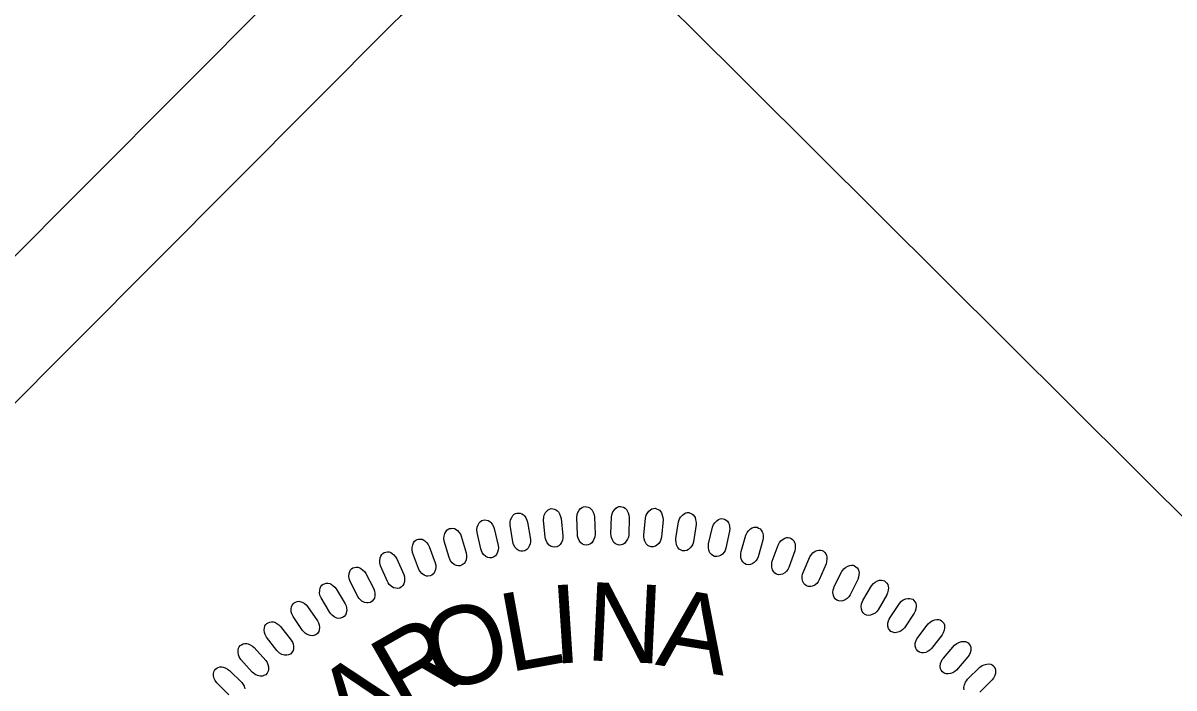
# Model space of a CAD drawing. Extents: x 1481763 to 1495577, y 493394 to 506245.
# Drawn here: x 1489881 to 1490047.4, y 499065.5 to 499161.7 of the extents above; entities that cross this region are included whole.
import ezdxf

# ---------------------------------------------------------------- set-up
doc = ezdxf.new("R2010")
doc.units = 0
for name, color, linetype in [('Old_Level_9', 7, 'Continuous'), ('Sheet Sticker Exception Certification CELL', 7, 'Continuous'), ('Sheet Title CELL', 7, 'Continuous')]:
    doc.layers.add(name, color=color, linetype=linetype)

msp = doc.modelspace()

# ---------------------------------------------------------------- linework, layer by layer
at = {"layer": 'Old_Level_9'}
for points in [[(1489956.48, 499087.36), (1489956.24, 499089.81), (1489956.28, 499090.25), (1489956.35, 499090.54), (1489956.54, 499090.9), (1489956.72, 499091.13), (1489956.92, 499091.31), (1489957.12, 499091.41), (1489957.35, 499091.47), (1489957.57, 499091.46), (1489957.82, 499091.42), (1489958.04, 499091.32), (1489958.26, 499091.14), (1489958.4, 499091), (1489958.56, 499090.71), (1489958.71, 499090.36), (1489958.79, 499090.05), (1489959.04, 499087.55), (1489959.03, 499087.21), (1489958.97, 499086.92), (1489958.82, 499086.59), (1489958.63, 499086.29), (1489958.45, 499086.11), (1489958.15, 499085.96), (1489957.85, 499085.89), (1489957.55, 499085.94), (1489957.33, 499086.02), (1489957.06, 499086.2), (1489956.79, 499086.51), (1489956.62, 499086.86), (1489956.53, 499087.11)], [(1489961.13, 499087.74), (1489961.04, 499090.19), (1489961.1, 499090.63), (1489961.2, 499090.91), (1489961.41, 499091.26), (1489961.6, 499091.49), (1489961.82, 499091.65), (1489962.02, 499091.74), (1489962.25, 499091.79), (1489962.47, 499091.75), (1489962.71, 499091.7), (1489962.93, 499091.59), (1489963.14, 499091.4), (1489963.27, 499091.24), (1489963.41, 499090.95), (1489963.54, 499090.59), (1489963.6, 499090.28), (1489963.7, 499087.76), (1489963.66, 499087.42), (1489963.58, 499087.14), (1489963.41, 499086.82), (1489963.2, 499086.53), (1489963.01, 499086.36), (1489962.7, 499086.23), (1489962.4, 499086.18), (1489962.1, 499086.25), (1489961.89, 499086.35), (1489961.63, 499086.54), (1489961.38, 499086.87), (1489961.23, 499087.22), (1489961.16, 499087.48)], [(1489965.99, 499087.82), (1489966.06, 499090.27), (1489966.15, 499090.71), (1489966.26, 499090.99), (1489966.49, 499091.32), (1489966.69, 499091.53), (1489966.92, 499091.68), (1489967.14, 499091.76), (1489967.36, 499091.79), (1489967.58, 499091.74), (1489967.82, 499091.68), (1489968.03, 499091.55), (1489968.23, 499091.35), (1489968.34, 499091.18), (1489968.47, 499090.88), (1489968.58, 499090.52), (1489968.62, 499090.2), (1489968.55, 499087.68), (1489968.5, 499087.35), (1489968.4, 499087.07), (1489968.21, 499086.76), (1489967.98, 499086.48), (1489967.78, 499086.33), (1489967.46, 499086.22), (1489967.16, 499086.19), (1489966.87, 499086.28), (1489966.66, 499086.38), (1489966.41, 499086.59), (1489966.19, 499086.94), (1489966.06, 499087.3), (1489966.01, 499087.56)], [(1489970.74, 499087.64), (1489970.96, 499090.08), (1489971.08, 499090.51), (1489971.21, 499090.78), (1489971.46, 499091.1), (1489971.68, 499091.3), (1489971.91, 499091.44), (1489972.13, 499091.5), (1489972.36, 499091.52), (1489972.58, 499091.46), (1489972.81, 499091.37), (1489973.01, 499091.24), (1489973.2, 499091.02), (1489973.3, 499090.85), (1489973.41, 499090.54), (1489973.49, 499090.17), (1489973.51, 499089.85), (1489973.29, 499087.34), (1489973.22, 499087.01), (1489973.1, 499086.74), (1489972.89, 499086.44), (1489972.64, 499086.18), (1489972.43, 499086.04), (1489972.11, 499085.95), (1489971.81, 499085.94), (1489971.52, 499086.05), (1489971.32, 499086.16), (1489971.09, 499086.39), (1489970.88, 499086.75), (1489970.78, 499087.12), (1489970.74, 499087.38)], [(1489975.38, 499087.14), (1489975.76, 499089.56), (1489975.9, 499089.98), (1489976.05, 499090.24), (1489976.32, 499090.54), (1489976.55, 499090.73), (1489976.79, 499090.85), (1489977.01, 499090.9), (1489977.24, 499090.9), (1489977.46, 499090.83), (1489977.68, 499090.73), (1489977.87, 499090.58), (1489978.05, 499090.35), (1489978.14, 499090.18), (1489978.23, 499089.86), (1489978.29, 499089.49), (1489978.29, 499089.17), (1489977.91, 499086.68), (1489977.81, 499086.35), (1489977.68, 499086.09), (1489977.46, 499085.8), (1489977.19, 499085.56), (1489976.97, 499085.43), (1489976.65, 499085.36), (1489976.34, 499085.37), (1489976.06, 499085.5), (1489975.87, 499085.63), (1489975.65, 499085.86), (1489975.47, 499086.24), (1489975.39, 499086.61), (1489975.37, 499086.88)], [(1489947.17, 499085.64), (1489946.63, 499088.03), (1489946.61, 499088.48), (1489946.65, 499088.77), (1489946.79, 499089.15), (1489946.94, 499089.41), (1489947.12, 499089.62), (1489947.31, 499089.74), (1489947.52, 499089.83), (1489947.74, 499089.84), (1489947.99, 499089.83), (1489948.22, 499089.76), (1489948.47, 499089.61), (1489948.62, 499089.48), (1489948.82, 499089.22), (1489949.01, 499088.9), (1489949.13, 499088.6), (1489949.69, 499086.15), (1489949.72, 499085.81), (1489949.7, 499085.51), (1489949.59, 499085.16), (1489949.44, 499084.84), (1489949.28, 499084.64), (1489949, 499084.46), (1489948.72, 499084.35), (1489948.41, 499084.37), (1489948.18, 499084.42), (1489947.89, 499084.55), (1489947.58, 499084.83), (1489947.37, 499085.15), (1489947.26, 499085.39)], [(1489951.8, 499086.68), (1489951.41, 499089.1), (1489951.41, 499089.55), (1489951.47, 499089.84), (1489951.64, 499090.21), (1489951.8, 499090.46), (1489951.99, 499090.65), (1489952.19, 499090.76), (1489952.4, 499090.84), (1489952.63, 499090.83), (1489952.88, 499090.81), (1489953.1, 499090.73), (1489953.34, 499090.56), (1489953.49, 499090.42), (1489953.67, 499090.15), (1489953.84, 499089.81), (1489953.94, 499089.5), (1489954.35, 499087.03), (1489954.36, 499086.68), (1489954.31, 499086.39), (1489954.19, 499086.05), (1489954.01, 499085.74), (1489953.84, 499085.55), (1489953.55, 499085.38), (1489953.26, 499085.3), (1489952.95, 499085.33), (1489952.73, 499085.39), (1489952.45, 499085.55), (1489952.16, 499085.85), (1489951.97, 499086.18), (1489951.87, 499086.43)], [(1489980.11, 499086.38), (1489980.65, 499088.77), (1489980.81, 499089.18), (1489980.98, 499089.43), (1489981.27, 499089.72), (1489981.51, 499089.89), (1489981.76, 499090), (1489981.98, 499090.03), (1489982.21, 499090.02), (1489982.42, 499089.93), (1489982.64, 499089.82), (1489982.82, 499089.66), (1489982.98, 499089.42), (1489983.06, 499089.24), (1489983.13, 499088.91), (1489983.17, 499088.54), (1489983.14, 499088.22), (1489982.61, 499085.76), (1489982.49, 499085.44), (1489982.35, 499085.19), (1489982.1, 499084.91), (1489981.82, 499084.69), (1489981.6, 499084.58), (1489981.27, 499084.53), (1489980.97, 499084.55), (1489980.69, 499084.7), (1489980.51, 499084.84), (1489980.3, 499085.09), (1489980.14, 499085.47), (1489980.09, 499085.85), (1489980.09, 499086.12)], [(1489942.59, 499084.4), (1489941.9, 499086.75), (1489941.85, 499087.19), (1489941.87, 499087.49), (1489941.99, 499087.88), (1489942.12, 499088.14), (1489942.29, 499088.36), (1489942.46, 499088.5), (1489942.67, 499088.6), (1489942.9, 499088.62), (1489943.14, 499088.63), (1489943.38, 499088.58), (1489943.63, 499088.44), (1489943.79, 499088.32), (1489944.01, 499088.07), (1489944.22, 499087.76), (1489944.35, 499087.47), (1489945.07, 499085.06), (1489945.13, 499084.72), (1489945.12, 499084.43), (1489945.04, 499084.07), (1489944.9, 499083.74), (1489944.76, 499083.53), (1489944.49, 499083.33), (1489944.21, 499083.21), (1489943.9, 499083.2), (1489943.67, 499083.24), (1489943.37, 499083.36), (1489943.05, 499083.62), (1489942.82, 499083.92), (1489942.69, 499084.16)], [(1489984.8, 499085.27), (1489985.48, 499087.63), (1489985.67, 499088.03), (1489985.85, 499088.27), (1489986.16, 499088.53), (1489986.41, 499088.69), (1489986.67, 499088.78), (1489986.89, 499088.8), (1489987.12, 499088.77), (1489987.32, 499088.67), (1489987.53, 499088.55), (1489987.7, 499088.38), (1489987.85, 499088.13), (1489987.92, 499087.94), (1489987.97, 499087.62), (1489987.98, 499087.24), (1489987.94, 499086.92), (1489987.25, 499084.5), (1489987.12, 499084.19), (1489986.95, 499083.94), (1489986.69, 499083.69), (1489986.4, 499083.48), (1489986.17, 499083.38), (1489985.83, 499083.35), (1489985.53, 499083.4), (1489985.27, 499083.56), (1489985.1, 499083.71), (1489984.91, 499083.97), (1489984.77, 499084.36), (1489984.74, 499084.75), (1489984.76, 499085.01)], [(1489938.15, 499082.82), (1489937.32, 499085.13), (1489937.24, 499085.56), (1489937.24, 499085.86), (1489937.34, 499086.26), (1489937.44, 499086.53), (1489937.6, 499086.76), (1489937.77, 499086.9), (1489937.97, 499087.02), (1489938.19, 499087.05), (1489938.44, 499087.08), (1489938.68, 499087.04), (1489938.94, 499086.92), (1489939.11, 499086.81), (1489939.34, 499086.58), (1489939.57, 499086.28), (1489939.72, 499086), (1489940.59, 499083.64), (1489940.66, 499083.3), (1489940.67, 499083.01), (1489940.61, 499082.65), (1489940.5, 499082.31), (1489940.37, 499082.09), (1489940.12, 499081.87), (1489939.85, 499081.74), (1489939.54, 499081.71), (1489939.31, 499081.73), (1489939, 499081.83), (1489938.66, 499082.07), (1489938.41, 499082.36), (1489938.27, 499082.59)], [(1489989.31, 499083.9), (1489990.14, 499086.21), (1489990.36, 499086.6), (1489990.55, 499086.83), (1489990.88, 499087.07), (1489991.13, 499087.21), (1489991.4, 499087.28), (1489991.62, 499087.29), (1489991.85, 499087.25), (1489992.05, 499087.14), (1489992.25, 499087), (1489992.41, 499086.82), (1489992.54, 499086.56), (1489992.6, 499086.37), (1489992.62, 499086.04), (1489992.61, 499085.66), (1489992.55, 499085.35), (1489991.71, 499082.98), (1489991.56, 499082.67), (1489991.38, 499082.44), (1489991.1, 499082.2), (1489990.8, 499082.01), (1489990.56, 499081.93), (1489990.22, 499081.92), (1489989.93, 499081.98), (1489989.68, 499082.16), (1489989.51, 499082.33), (1489989.34, 499082.6), (1489989.23, 499083), (1489989.22, 499083.38), (1489989.26, 499083.65)], [(1489933.67, 499080.96), (1489932.69, 499083.21), (1489932.58, 499083.64), (1489932.56, 499083.94), (1489932.64, 499084.34), (1489932.73, 499084.62), (1489932.87, 499084.86), (1489933.03, 499085.01), (1489933.22, 499085.14), (1489933.44, 499085.19), (1489933.68, 499085.23), (1489933.92, 499085.21), (1489934.19, 499085.11), (1489934.37, 499085.01), (1489934.61, 499084.79), (1489934.86, 499084.51), (1489935.03, 499084.23), (1489936.05, 499081.93), (1489936.14, 499081.6), (1489936.17, 499081.31), (1489936.13, 499080.95), (1489936.04, 499080.6), (1489935.92, 499080.38), (1489935.68, 499080.14), (1489935.43, 499079.99), (1489935.12, 499079.94), (1489934.89, 499079.95), (1489934.58, 499080.03), (1489934.22, 499080.25), (1489933.95, 499080.52), (1489933.8, 499080.74)], [(1489993.76, 499082.24), (1489994.73, 499084.49), (1489994.97, 499084.86), (1489995.18, 499085.08), (1489995.52, 499085.3), (1489995.78, 499085.43), (1489996.05, 499085.48), (1489996.28, 499085.48), (1489996.5, 499085.42), (1489996.69, 499085.3), (1489996.88, 499085.15), (1489997.03, 499084.96), (1489997.14, 499084.69), (1489997.19, 499084.5), (1489997.19, 499084.17), (1489997.16, 499083.79), (1489997.08, 499083.48), (1489996.1, 499081.17), (1489995.92, 499080.87), (1489995.73, 499080.65), (1489995.44, 499080.43), (1489995.12, 499080.26), (1489994.88, 499080.19), (1489994.54, 499080.21), (1489994.25, 499080.29), (1489994.01, 499080.48), (1489993.86, 499080.65), (1489993.7, 499080.94), (1489993.62, 499081.34), (1489993.64, 499081.73), (1489993.68, 499081.99)], [(1489929.4, 499078.76), (1489928.28, 499080.95), (1489928.15, 499081.37), (1489928.12, 499081.67), (1489928.16, 499082.07), (1489928.24, 499082.36), (1489928.36, 499082.6), (1489928.51, 499082.77), (1489928.69, 499082.9), (1489928.91, 499082.97), (1489929.15, 499083.03), (1489929.39, 499083.02), (1489929.67, 499082.93), (1489929.85, 499082.84), (1489930.1, 499082.64), (1489930.37, 499082.37), (1489930.56, 499082.11), (1489931.72, 499079.88), (1489931.83, 499079.56), (1489931.88, 499079.27), (1489931.87, 499078.9), (1489931.79, 499078.55), (1489931.69, 499078.32), (1489931.47, 499078.07), (1489931.22, 499077.9), (1489930.92, 499077.84), (1489930.69, 499077.83), (1489930.37, 499077.89), (1489930, 499078.08), (1489929.72, 499078.34), (1489929.55, 499078.55)], [(1489998.27, 499080.21), (1489999.38, 499082.4), (1489999.65, 499082.76), (1489999.87, 499082.96), (1490000.22, 499083.16), (1490000.49, 499083.27), (1490000.77, 499083.31), (1490000.99, 499083.28), (1490001.21, 499083.22), (1490001.39, 499083.08), (1490001.57, 499082.92), (1490001.71, 499082.72), (1490001.8, 499082.44), (1490001.84, 499082.25), (1490001.82, 499081.92), (1490001.77, 499081.55), (1490001.66, 499081.24), (1490000.54, 499078.99), (1490000.35, 499078.71), (1490000.14, 499078.5), (1489999.83, 499078.3), (1489999.51, 499078.15), (1489999.26, 499078.1), (1489998.93, 499078.13), (1489998.64, 499078.23), (1489998.41, 499078.44), (1489998.27, 499078.62), (1489998.13, 499078.92), (1489998.07, 499079.33), (1489998.12, 499079.71), (1489998.18, 499079.97)], [(1490002.4, 499078.2), (1490003.65, 499080.31), (1490003.93, 499080.65), (1490004.17, 499080.84), (1490004.53, 499081.02), (1490004.81, 499081.11), (1490005.09, 499081.13), (1490005.31, 499081.1), (1490005.52, 499081.02), (1490005.69, 499080.87), (1490005.87, 499080.69), (1490005.99, 499080.49), (1490006.07, 499080.21), (1490006.09, 499080.01), (1490006.05, 499079.68), (1490005.97, 499079.31), (1490005.85, 499079.02), (1490004.59, 499076.84), (1490004.38, 499076.57), (1490004.16, 499076.38), (1490003.84, 499076.19), (1490003.51, 499076.07), (1490003.26, 499076.03), (1490002.93, 499076.08), (1490002.65, 499076.2), (1490002.43, 499076.42), (1490002.3, 499076.61), (1490002.18, 499076.92), (1490002.15, 499077.33), (1490002.22, 499077.71), (1490002.3, 499077.96)], [(1489925.34, 499076.45), (1489924.09, 499078.56), (1489923.93, 499078.98), (1489923.88, 499079.27), (1489923.9, 499079.68), (1489923.95, 499079.96), (1489924.07, 499080.22), (1489924.2, 499080.39), (1489924.38, 499080.54), (1489924.59, 499080.62), (1489924.83, 499080.69), (1489925.07, 499080.7), (1489925.35, 499080.63), (1489925.53, 499080.55), (1489925.8, 499080.37), (1489926.09, 499080.12), (1489926.29, 499079.87), (1489927.59, 499077.71), (1489927.72, 499077.4), (1489927.78, 499077.11), (1489927.79, 499076.75), (1489927.74, 499076.39), (1489927.66, 499076.16), (1489927.45, 499075.89), (1489927.21, 499075.71), (1489926.92, 499075.62), (1489926.68, 499075.6), (1489926.36, 499075.64), (1489925.98, 499075.81), (1489925.69, 499076.05), (1489925.5, 499076.24)], [(1489921.42, 499073.85), (1489920.04, 499075.88), (1489919.85, 499076.28), (1489919.78, 499076.57), (1489919.78, 499076.98), (1489919.81, 499077.27), (1489919.91, 499077.53), (1489920.04, 499077.71), (1489920.2, 499077.87), (1489920.41, 499077.97), (1489920.64, 499078.05), (1489920.88, 499078.07), (1489921.16, 499078.02), (1489921.35, 499077.96), (1489921.63, 499077.79), (1489921.93, 499077.56), (1489922.15, 499077.32), (1489923.58, 499075.25), (1489923.73, 499074.95), (1489923.81, 499074.67), (1489923.85, 499074.3), (1489923.82, 499073.94), (1489923.75, 499073.7), (1489923.56, 499073.43), (1489923.33, 499073.23), (1489923.04, 499073.12), (1489922.81, 499073.09), (1489922.49, 499073.11), (1489922.1, 499073.26), (1489921.79, 499073.48), (1489921.59, 499073.66)], [(1490006.32, 499075.74), (1490007.69, 499077.77), (1490008, 499078.09), (1490008.24, 499078.27), (1490008.62, 499078.42), (1490008.9, 499078.49), (1490009.18, 499078.5), (1490009.4, 499078.45), (1490009.6, 499078.36), (1490009.77, 499078.2), (1490009.93, 499078.01), (1490010.04, 499077.8), (1490010.1, 499077.51), (1490010.11, 499077.32), (1490010.05, 499076.99), (1490009.95, 499076.63), (1490009.81, 499076.34), (1490008.41, 499074.25), (1490008.18, 499073.99), (1490007.95, 499073.81), (1490007.63, 499073.65), (1490007.28, 499073.54), (1490007.04, 499073.52), (1490006.71, 499073.6), (1490006.44, 499073.73), (1490006.23, 499073.97), (1490006.12, 499074.16), (1490006.02, 499074.47), (1490006.01, 499074.89), (1490006.1, 499075.26), (1490006.2, 499075.51)], [(1489917.71, 499070.94), (1489916.21, 499072.88), (1489915.99, 499073.27), (1489915.91, 499073.55), (1489915.87, 499073.96), (1489915.89, 499074.25), (1489915.97, 499074.52), (1489916.09, 499074.71), (1489916.24, 499074.88), (1489916.44, 499074.98), (1489916.67, 499075.08), (1489916.91, 499075.12), (1489917.19, 499075.09), (1489917.39, 499075.04), (1489917.68, 499074.88), (1489917.99, 499074.67), (1489918.22, 499074.45), (1489919.78, 499072.47), (1489919.95, 499072.18), (1489920.05, 499071.9), (1489920.11, 499071.54), (1489920.1, 499071.18), (1489920.05, 499070.94), (1489919.87, 499070.65), (1489919.66, 499070.44), (1489919.37, 499070.32), (1489919.15, 499070.27), (1489918.82, 499070.27), (1489918.43, 499070.39), (1489918.1, 499070.59), (1489917.89, 499070.76)], [(1490010.34, 499072.86), (1490011.84, 499074.8), (1490012.16, 499075.1), (1490012.42, 499075.26), (1490012.8, 499075.39), (1490013.09, 499075.45), (1490013.36, 499075.44), (1490013.58, 499075.37), (1490013.78, 499075.27), (1490013.93, 499075.1), (1490014.09, 499074.9), (1490014.18, 499074.68), (1490014.22, 499074.4), (1490014.22, 499074.2), (1490014.14, 499073.88), (1490014.02, 499073.52), (1490013.86, 499073.24), (1490012.33, 499071.24), (1490012.09, 499071), (1490011.85, 499070.84), (1490011.51, 499070.69), (1490011.16, 499070.61), (1490010.91, 499070.6), (1490010.59, 499070.7), (1490010.33, 499070.85), (1490010.14, 499071.1), (1490010.04, 499071.3), (1490009.96, 499071.62), (1490009.98, 499072.03), (1490010.09, 499072.4), (1490010.2, 499072.64)], [(1489914.13, 499067.84), (1489912.5, 499069.68), (1489912.27, 499070.06), (1489912.16, 499070.34), (1489912.11, 499070.74), (1489912.11, 499071.03), (1489912.17, 499071.3), (1489912.27, 499071.5), (1489912.41, 499071.68), (1489912.61, 499071.79), (1489912.83, 499071.91), (1489913.06, 499071.96), (1489913.35, 499071.95), (1489913.55, 499071.91), (1489913.85, 499071.77), (1489914.17, 499071.58), (1489914.42, 499071.37), (1489916.1, 499069.5), (1489916.29, 499069.22), (1489916.4, 499068.95), (1489916.48, 499068.59), (1489916.5, 499068.23), (1489916.46, 499067.98), (1489916.3, 499067.69), (1489916.11, 499067.46), (1489915.83, 499067.32), (1489915.61, 499067.26), (1489915.28, 499067.24), (1489914.88, 499067.33), (1489914.54, 499067.51), (1489914.32, 499067.67)], [(1490014.03, 499069.87), (1490015.65, 499071.71), (1490016, 499071.99), (1490016.26, 499072.13), (1490016.65, 499072.24), (1490016.94, 499072.28), (1490017.22, 499072.25), (1490017.42, 499072.17), (1490017.62, 499072.05), (1490017.76, 499071.87), (1490017.9, 499071.67), (1490017.98, 499071.44), (1490018.01, 499071.16), (1490017.99, 499070.96), (1490017.89, 499070.64), (1490017.75, 499070.29), (1490017.57, 499070.03), (1490015.92, 499068.13), (1490015.67, 499067.9), (1490015.41, 499067.75), (1490015.07, 499067.63), (1490014.72, 499067.57), (1490014.46, 499067.58), (1490014.15, 499067.69), (1490013.9, 499067.86), (1490013.73, 499068.12), (1490013.63, 499068.33), (1490013.58, 499068.65), (1490013.62, 499069.06), (1490013.76, 499069.42), (1490013.88, 499069.65)]]:
    msp.add_lwpolyline(points, close=True, dxfattribs=at)
for points in [[(1489910.76, 499064.54), (1489909.03, 499066.27), (1489908.77, 499066.63), (1489908.64, 499066.9), (1489908.56, 499067.3), (1489908.54, 499067.59), (1489908.59, 499067.86), (1489908.68, 499068.07), (1489908.81, 499068.26), (1489909, 499068.39), (1489909.21, 499068.51), (1489909.44, 499068.58), (1489909.73, 499068.58), (1489909.93, 499068.56), (1489910.23, 499068.44), (1489910.57, 499068.27), (1489910.83, 499068.08), (1489912.62, 499066.32), (1489912.83, 499066.04), (1489912.96, 499065.78), (1489913.06, 499065.43)], [(1490017.05, 499065.28), (1490017.01, 499065.6), (1490017.08, 499066.01), (1490017.24, 499066.36), (1490017.38, 499066.59), (1490017.54, 499066.79), (1490019.28, 499068.53), (1490019.64, 499068.79), (1490019.91, 499068.91), (1490020.31, 499068.99), (1490020.6, 499069.01), (1490020.87, 499068.97), (1490021.07, 499068.88), (1490021.26, 499068.74), (1490021.39, 499068.56), (1490021.52, 499068.35), (1490021.58, 499068.12), (1490021.59, 499067.83), (1490021.56, 499067.63), (1490021.45, 499067.32), (1490021.28, 499066.98), (1490021.09, 499066.73), (1490019.32, 499064.93)]]:
    msp.add_lwpolyline(points, dxfattribs=at)
at = {"layer": 'Sheet Title CELL'}
for p, q in [((1487288.78, 496526.16), (1490294.79, 499544.69)), ((1489511.58, 498736.96), (1489934.47, 499161.61)), ((1490317.02, 498823), (1489976.9, 499161.7))]:
    msp.add_line(p, q, dxfattribs=at)
msp.add_arc((1489955.73, 499140.44), 30, 45.1191, 135.1191, dxfattribs=at)

# ---------------------------------------------------------------- texts
at = {"layer": 'Old_Level_9'}
for s, rotation, p in [('L', 10.26, (1489951.26, 499067.8)), ('I', 3.7706, (1489957.68, 499069.01)), ('N', 357.2813, (1489962.24, 499069.56)), ('A', 350.7919, (1489972.29, 499068.93)), ('O', 16.7494, (1489940.99, 499064.67)), ('R', 29.7281, (1489935.89, 499061.4)), ('A', 36.2174, (1489928.83, 499056.56))]:
    msp.add_text(s, height=11.34, rotation=rotation, dxfattribs=at).set_placement(p)
at = {"layer": 'Sheet Sticker Exception Certification CELL'}
for s, p in [('DOCUMENT NOT CONSIDERED FINAL', (1489709.46, 499055.55)), ('UNLESS ALL SIGNATURES COMPLETED', (1489716.57, 499030.63))]:
    msp.add_text(s, height=13.5, rotation=45.1191, dxfattribs=at).set_placement(p)

doc.saveas('drawing.dxf')
